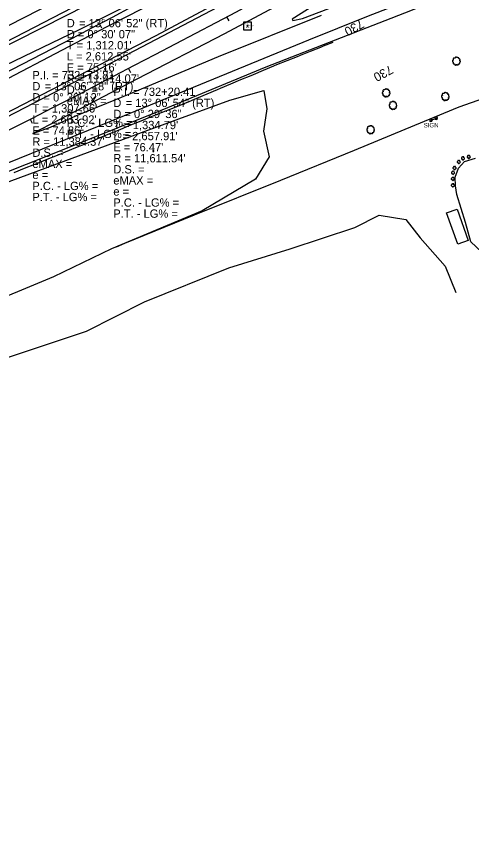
# Model space of a CAD drawing. Extents: x 1901471 to 1963503, y 756461 to 799997.
# Drawn here: x 1910625 to 1911035, y 760274 to 761023 of the extents above; entities that cross this region are included whole.
import ezdxf

# ---------------------------------------------------------------- set-up
doc = ezdxf.new("R2010")
doc.units = 0
for name, color, linetype in [('Default', 7, 'Continuous'), ('RD_DTM_BkLn1', 7, 'Continuous'), ('RD_EX_Bldg', 7, 'Continuous'), ('RD_EX_Conc', 7, 'Continuous'), ('RD_EX_Fence_Other', 7, 'Continuous'), ('RD_EX_H2O', 7, 'Continuous'), ('RD_EX_Road', 7, 'Continuous'), ('RD_EX_Road_txCode', 7, 'Continuous'), ('RD_EX_VEG', 7, 'Continuous'), ('RD_HC_Cl', 7, 'Continuous'), ('RD_HC_Data', 7, 'Continuous'), ('RD_HC_Data_Tic', 7, 'Continuous'), ('RD_HC_Survey', 7, 'Continuous'), ('RD_HC_TX_Sta50', 7, 'Continuous'), ('RD_HC_txCode', 7, 'Continuous'), ('RD_SMD_Locator', 7, 'Continuous')]:
    doc.layers.add(name, color=color, linetype=linetype)

# ---------------------------------------------------------------- blocks, each defined once
blk = doc.blocks.new('T2')
at = {"layer": 'RD_EX_VEG'}
for points in [[(0.05233333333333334, 7.213166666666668), (-0.24750000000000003, 7.238166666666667), (-0.5723333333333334, 7.138166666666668), (-0.8222500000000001, 7.038250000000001), (-1.0471666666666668, 6.963250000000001), (-1.2720833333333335, 6.863250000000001), (-1.5719166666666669, 6.688416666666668), (-1.7968333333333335, 6.488416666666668), (-1.9218333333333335, 6.2385833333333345), (-1.9718333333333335, 6.013666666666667), (-2.0217500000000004, 5.738833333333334), (-2.0217500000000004, 5.563833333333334), (-2.146666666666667, 5.538833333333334), (-2.296666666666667, 5.563833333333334), (-2.5465000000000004, 5.638833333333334), (-2.796416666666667, 5.638833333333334), (-3.0463333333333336, 5.638833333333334), (-3.3961666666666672, 5.613833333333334), (-3.7460000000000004, 5.613833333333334), (-4.020833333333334, 5.563833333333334), (-4.345750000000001, 5.513916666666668), (-4.720583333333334, 5.389000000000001), (-5.0704166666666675, 5.264000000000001), (-5.37025, 5.014083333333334), (-5.620166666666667, 4.539333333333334), (-5.745166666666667, 4.189500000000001), (-5.895083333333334, 3.9395833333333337), (-5.745166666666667, 3.489833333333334), (-5.570166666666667, 3.139916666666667), (-5.545250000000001, 2.9400000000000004), (-5.470250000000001, 2.5152500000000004), (-5.37025, 2.2903333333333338), (-5.245333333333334, 2.0903333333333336), (-5.320250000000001, 2.065416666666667), (-5.695166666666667, 2.015416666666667), (-5.995000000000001, 1.9155000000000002), (-6.419833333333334, 1.6905833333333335), (-6.644750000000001, 1.465666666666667), (-6.744750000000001, 1.1407500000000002), (-6.769666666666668, 0.7909166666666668), (-6.869583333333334, 0.5910833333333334), (-6.944583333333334, 0.3161666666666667), (-6.969583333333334, 0.2411666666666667), (-7.019583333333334, -0.08366666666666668), (-6.9195833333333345, -0.5335000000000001), (-6.894583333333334, -0.8833333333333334), (-6.769666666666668, -1.1082500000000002), (-6.619750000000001, -1.2830833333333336), (-6.444833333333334, -1.5330000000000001), (-6.045000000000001, -1.7579166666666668), (-5.7201666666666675, -1.8579166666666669), (-5.520250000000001, -1.8828333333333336), (-5.695166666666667, -2.382666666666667), (-5.745166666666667, -2.7325000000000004), (-5.870083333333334, -3.132333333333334), (-5.870083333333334, -3.2072500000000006), (-5.920000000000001, -3.682083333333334), (-5.770166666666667, -4.007000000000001), (-5.695166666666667, -4.38175), (-5.520250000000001, -4.606666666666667), (-5.245333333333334, -4.906583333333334), (-4.9205000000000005, -5.131416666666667), (-4.420666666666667, -5.256416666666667), (-4.020833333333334, -5.231416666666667), (-3.4460833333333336, -5.056500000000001), (-3.1962500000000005, -4.9815000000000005), (-3.2212500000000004, -5.156416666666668), (-3.1962500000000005, -5.531333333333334), (-3.1962500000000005, -5.956083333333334), (-3.0463333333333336, -6.280916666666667), (-2.946333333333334, -6.555833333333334), (-2.796416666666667, -6.805750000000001), (-2.4715000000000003, -7.030583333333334), (-2.07175, -7.1055833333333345), (-1.6469166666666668, -7.2555000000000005), (-1.1970833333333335, -7.330500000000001), (-0.6973333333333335, -7.355500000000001), (-0.09758333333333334, -7.205583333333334), (0.17725000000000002, -7.080583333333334), (0.27725000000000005, -6.905666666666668), (0.47716666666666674, -6.530833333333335), (0.4271666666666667, -6.3059166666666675), (0.4521666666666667, -5.706166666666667), (0.5520833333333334, -5.881166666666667), (0.7270833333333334, -6.231000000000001), (1.2268333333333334, -6.530833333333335), (1.626666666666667, -6.705750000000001), (2.101416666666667, -6.8557500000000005), (2.4013333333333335, -6.930666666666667), (2.8760833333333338, -6.8557500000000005), (3.2510000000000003, -6.780750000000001), (3.6257500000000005, -6.655750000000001), (3.9256666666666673, -6.380916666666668), (4.100583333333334, -6.106000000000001), (4.1505833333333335, -5.831166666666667), (4.2255, -5.456333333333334), (4.275500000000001, -5.281416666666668)], [(4.275500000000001, -5.281416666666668), (4.200583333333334, -5.106416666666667), (4.1505833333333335, -4.856583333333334), (4.2255, -4.881583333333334), (4.4004166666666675, -4.931583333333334), (4.675333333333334, -5.056500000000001), (4.900250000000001, -5.131416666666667), (5.225083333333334, -5.106416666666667), (5.500000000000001, -5.006500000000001), (5.949750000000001, -4.731583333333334), (6.224666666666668, -4.256833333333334), (6.499500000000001, -3.8570000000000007), (6.5745000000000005, -3.5321666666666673), (6.524500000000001, -3.3072500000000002), (6.499500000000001, -2.8075000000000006), (6.299583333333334, -2.5575833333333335), (6.249583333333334, -2.432666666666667), (6.1496666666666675, -2.0328333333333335), (6.224666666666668, -1.9828333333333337), (6.499500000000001, -1.9328333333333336), (6.874333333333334, -1.8079166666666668), (7.149250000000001, -1.6830000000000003), (7.374166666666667, -1.5080000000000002), (7.449083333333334, -1.2830833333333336), (7.424166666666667, -0.8833333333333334), (7.4740833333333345, -0.48350000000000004), (7.399166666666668, -0.3335), (7.299166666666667, -0.1836666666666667), (7.224166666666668, 0.016333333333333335), (7.074250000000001, 0.16616666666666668), (6.974333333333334, 0.3161666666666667), (6.874333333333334, 0.41608333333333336), (6.749416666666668, 0.5660833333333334), (6.5745000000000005, 0.6910000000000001), (6.424583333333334, 0.7410000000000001), (6.374583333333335, 0.8909166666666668), (6.524500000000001, 1.0908333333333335), (6.5745000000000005, 1.1907500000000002), (6.599416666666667, 1.4156666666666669), (6.824416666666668, 1.7655000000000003), (6.874333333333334, 2.1653333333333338), (6.824416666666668, 2.590166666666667), (6.774416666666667, 2.8650833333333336), (6.624416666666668, 3.139916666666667), (6.424583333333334, 3.3898333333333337), (6.299583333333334, 3.5647500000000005), (6.124666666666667, 3.689666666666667), (5.799833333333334, 3.814666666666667), (5.549916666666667, 3.864583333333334), (5.200083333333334, 3.864583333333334), (5.000166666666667, 3.9145833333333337), (5.025166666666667, 3.964583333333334), (5.025166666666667, 4.1145000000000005), (5.025166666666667, 4.389416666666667), (4.950166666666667, 4.839166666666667), (4.800250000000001, 5.339), (4.800250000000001, 5.364000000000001), (4.7002500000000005, 5.613833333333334), (4.475416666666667, 5.813750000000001), (4.3005, 5.913666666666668), (4.100583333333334, 6.038666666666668), (3.850666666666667, 6.063666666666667), (3.5508333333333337, 6.063666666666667), (3.2759166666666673, 6.013666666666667), (3.0760000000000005, 5.913666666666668), (2.9010833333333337, 5.788750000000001), (2.8260833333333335, 5.938666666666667), (2.726166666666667, 6.2385833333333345), (2.676166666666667, 6.3885000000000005), (2.52625, 6.563416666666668), (2.301416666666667, 6.7633333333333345), (1.8515000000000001, 6.888250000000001), (1.2268333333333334, 6.813333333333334), (0.9269166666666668, 6.613416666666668), (0.7770000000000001, 6.438500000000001), (0.7270833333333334, 6.563416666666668), (0.5270833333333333, 6.7633333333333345), (0.4271666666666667, 6.938250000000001), (0.25225000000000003, 7.063250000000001), (0.10233333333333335, 7.163166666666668), (0.0023333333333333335, 7.213166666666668)]]:
    blk.add_spline(points, degree=3, dxfattribs=at)
blk = doc.blocks.new('SB2')
at = {"layer": 'RD_EX_VEG'}
for centre, radius, start, end in [((-1.563757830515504, -0.1555935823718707), 1.256970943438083, 96.45178611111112, 294.73400833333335), ((-0.7210660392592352, 1.5471418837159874), 1.0835094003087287, 34.97628888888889, 204.7560222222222), ((1.0452472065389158, 1.7020636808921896), 0.9945285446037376, 308.76261111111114, 152.04674444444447), ((1.8396429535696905, -0.2793298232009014), 1.2180790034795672, 256.56668055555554, 98.10463055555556), ((0.2455500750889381, -1.5963122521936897), 1.3177675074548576, 166.88265555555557, 5.758930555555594)]:
    blk.add_arc(centre, radius, start, end, dxfattribs=at)
blk = doc.blocks.new('SIGNPOST')
at = {"layer": 'Default'}
for centre, start, end in [((7.776250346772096e-18, 0), 90.00000000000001, 270), ((-7.776250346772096e-18, 0), 270, 90)]:
    blk.add_arc(centre, 0.12700000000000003, start, end, dxfattribs=at)

msp = doc.modelspace()

# ---------------------------------------------------------------- linework, layer by layer
at = {"layer": 'Default'}
for p, q in [((1910704.7770000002, 760975.9843000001), (1910704.7770000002, 760974.2343000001)), ((1910705.6520000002, 760975.1093000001), (1910703.9020000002, 760975.1093000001)), ((1910674.5337000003, 760917.9531000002), (1910672.7837000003, 760917.9531000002)), ((1910673.6587000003, 760918.8281000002), (1910673.6587000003, 760917.0781000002)), ((1910748.9604000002, 760901.2138000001), (1910747.2104000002, 760901.2138000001)), ((1910748.0854000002, 760902.0888000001), (1910748.0854000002, 760900.3388000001))]:
    msp.add_line(p, q, dxfattribs=at)
at = {"layer": 'RD_DTM_BkLn1'}
msp.add_lwpolyline([(1910622.6313006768, 760881.9708389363), (1910631.922190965, 760885.6664134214), (1910641.2130812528, 760889.3619879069), (1910643.064136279, 760890.0982695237), (1910652.3296787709, 760893.8574605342), (1910661.5952212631, 760897.6166515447), (1910668.9848766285, 760900.6147626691), (1910678.2430306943, 760904.3939292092), (1910687.5011847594, 760908.173095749), (1910696.7593388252, 760911.9522622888), (1910698.0908794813, 760912.4957954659), (1910707.3210735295, 760916.3411197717), (1910716.5512675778, 760920.1864440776), (1910725.781461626, 760924.0317683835), (1910726.3550362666, 760924.270721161), (1910735.633826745, 760927.9940825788), (1910744.9126172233, 760931.7174439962), (1910750.0804685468, 760933.7911817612), (1910759.3518262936, 760937.5329661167), (1910768.6231840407, 760941.2747504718), (1910777.8945417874, 760945.0165348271), (1910778.174266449, 760945.1294276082), (1910787.3955065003, 760948.9938692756), (1910796.6167465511, 760952.8583109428), (1910805.8379866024, 760956.72275261), (1910808.6637450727, 760957.906972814), (1910817.8753922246, 760961.7951290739), (1910827.087039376, 760965.6832853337), (1910836.2986865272, 760969.5714415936), (1910838.3418913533, 760970.4338606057), (1910847.5396088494, 760974.354475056), (1910856.7373263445, 760978.2750895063), (1910859.4643495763, 760979.4375090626), (1910868.782821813, 760983.0639470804), (1910878.1012940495, 760986.6903850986), (1910880.7117837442, 760987.7063004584), (1910889.9869461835, 760991.4417091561), (1910899.262108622, 760995.1771178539), (1910901.739897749, 760996.1750038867), (1910910.361455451, 760999.3981055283)], dxfattribs=at)
at = {"layer": 'RD_EX_Bldg'}
msp.add_lwpolyline([(1910998.4000000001, 760929.1900000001), (1911004.5700000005, 760931.3600000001)], dxfattribs=at)
at = {"layer": 'RD_EX_Conc'}
msp.add_lwpolyline([(1911022.6600000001, 760817.2200000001), (1911012.6700000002, 760845.4000000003), (1911022.0300000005, 760848.7200000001), (1911032.0200000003, 760820.5300000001)], close=True, dxfattribs=at)
at = {"layer": 'RD_EX_Fence_Other'}
for points in [[(1910580.8800000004, 760962.4200000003), (1910681.6500000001, 761011.1200000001), (1910824.1700000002, 761083.3400000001), (1910922.5400000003, 761136.0100000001), (1911091.9300000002, 761226.7000000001), (1911190.0700000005, 761280.4500000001), (1911287.4800000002, 761335.9900000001), (1911356.1000000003, 761375.9400000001), (1911439.3500000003, 761425.0100000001), (1911494.0600000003, 761458.0000000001), (1911589.0700000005, 761516.1800000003), (1911670.89, 761566.9300000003), (1911753.1900000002, 761616.7100000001), (1911806.6900000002, 761651.1400000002), (1911873.1500000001, 761696.0100000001), (1911887.0700000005, 761707.4100000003), (1911902.9000000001, 761720.8400000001)], [(1910714.7600000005, 760814.7800000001), (1910722.4100000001, 760818.1800000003), (1910785.1700000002, 760843.5400000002), (1910863.0500000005, 760874.82), (1910929.5100000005, 760902.1100000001), (1910983.9100000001, 760924.5000000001), (1911023.9700000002, 760941.0200000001), (1911091.6600000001, 760964.81), (1911105.1200000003, 760968.7500000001), (1911126.4600000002, 760976.6200000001), (1911147.9800000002, 760983.0900000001), (1911206.5700000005, 760997.7800000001), (1911243.1300000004, 761005.9200000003), (1911277.9400000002, 761012.9100000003), (1911301.9000000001, 761016.7600000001), (1911361.1900000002, 761026.56)], [(1911049.3800000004, 760805.1900000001), (1911034.4300000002, 760819.2000000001), (1911029.5500000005, 760836.83), (1911021.8300000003, 760862.0200000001), (1911020.7300000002, 760869.8900000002), (1911020.4200000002, 760877.6000000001), (1911023.2500000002, 760885.6300000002), (1911028.9200000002, 760891.7700000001), (1911038.6800000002, 760894.7600000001)]]:
    msp.add_lwpolyline(points, dxfattribs=at)
at = {"layer": 'RD_EX_H2O'}
msp.add_lwpolyline([(1909887.3000000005, 760625.4900000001), (1909934.2500000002, 760644.2800000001), (1910017.4500000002, 760680.8900000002), (1910099.7900000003, 760717.7600000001), (1910182.8200000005, 760756.1200000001), (1910236.6900000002, 760780.7800000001), (1910299.4900000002, 760809.82), (1910379.1900000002, 760848.3500000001), (1910428.0700000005, 760871.7000000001), (1910474.6600000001, 760894.6400000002), (1910580.3500000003, 760947.83), (1910696.5500000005, 761008.4900000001), (1910820.6200000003, 761072.3), (1910918.7000000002, 761126.2600000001), (1910925.4000000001, 761129.6100000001)], dxfattribs=at)
at = {"layer": 'RD_EX_Road'}
for points in [[(1910555.9700000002, 760966.08), (1910670.1800000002, 761023.8400000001), (1910732.0500000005, 761055.7700000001), (1910873.2500000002, 761130.9700000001), (1911013.1300000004, 761208.81), (1911171.1100000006, 761300.4700000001), (1911315.5900000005, 761384.8900000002), (1911418.2800000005, 761447.5900000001), (1911490.6900000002, 761492.6800000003), (1911567.3700000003, 761541.8800000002), (1911693.4300000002, 761624.33), (1911806.9700000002, 761700.8500000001), (1911899.7900000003, 761762.4000000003), (1911913.9200000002, 761772.8600000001), (1911956.0900000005, 761800.7400000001), (1911999.2000000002, 761829.9900000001)], [(1910580.0600000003, 760981.9200000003), (1910675.3100000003, 761030.7600000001), (1910773.4900000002, 761082.4000000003), (1910822.5800000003, 761108.6700000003), (1910885.9600000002, 761143.0300000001), (1910949.0700000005, 761177.6500000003), (1911003.9000000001, 761208.57), (1911064.7300000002, 761242.9300000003), (1911147.8600000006, 761291.2600000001), (1911222.0700000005, 761334.9300000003), (1911278.8100000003, 761368.4000000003), (1911332.8800000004, 761400.8500000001), (1911389.7500000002, 761435.3500000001), (1911475.1800000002, 761488.1300000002), (1911593.1200000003, 761563.1100000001), (1911672.9500000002, 761615.9000000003), (1911716.8100000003, 761645.5400000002), (1911779.8000000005, 761687.9400000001), (1911835.9000000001, 761725.3700000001), (1911887.8000000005, 761759.8600000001), (1911937.9100000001, 761793.33), (1911981.0100000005, 761822.4600000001), (1911998.6300000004, 761834.4100000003)], [(1910605.0100000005, 760930.3700000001), (1910750.1600000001, 761005.4100000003), (1910935.4500000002, 761104.6400000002), (1911040.1100000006, 761163.3900000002), (1911146.4200000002, 761223.7800000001), (1911234.6300000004, 761274.9600000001), (1911353.7700000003, 761346.3800000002), (1911491.3400000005, 761430.8), (1911642.0800000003, 761526.4100000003), (1911754.64, 761601.2900000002), (1911848.4400000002, 761663.33), (1911899.7900000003, 761698.2200000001), (1911993.7900000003, 761761.3900000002), (1912007.0300000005, 761770.2900000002)], [(1910589.3400000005, 760918.2400000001), (1910700.4300000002, 760975.7100000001), (1910824.9500000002, 761041.33), (1910949.7100000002, 761108.6300000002), (1911067.5200000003, 761174.7300000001), (1911186.5300000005, 761242.7500000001), (1911299.7700000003, 761309.2100000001), (1911392.1500000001, 761365.3600000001), (1911489.0800000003, 761425.2200000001), (1911580.9700000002, 761483.4000000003), (1911680.7900000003, 761547.5900000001), (1911813.4700000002, 761635.6400000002), (1911899.7800000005, 761693.1700000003), (1911931.1500000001, 761714.4000000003), (1911978.2000000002, 761746.0200000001), (1912007.6200000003, 761765.9400000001)], [(1910585.7400000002, 760878.06), (1910710.5000000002, 760928.56), (1910888.2900000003, 761001.6200000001), (1910940.6000000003, 761022.7400000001), (1910979.4700000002, 761037.9700000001), (1911045.6900000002, 761063.8800000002), (1911129.1800000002, 761091.6000000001), (1911194.2000000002, 761107.9100000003), (1911276.0200000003, 761125.07), (1911337.2000000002, 761133.4600000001), (1911445.1700000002, 761144.3800000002), (1911566.3400000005, 761156.2600000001), (1911684.3800000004, 761167.8900000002), (1911741.9700000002, 761173.4100000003), (1911807.2300000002, 761177.7300000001), (1911899.39, 761184.4200000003), (1911950.14, 761188.5300000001), (1911980.8000000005, 761190.4700000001), (1911998.7200000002, 761190.6900000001), (1912012.5400000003, 761189.3900000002), (1912024.6300000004, 761186.8)], [(1911898.8000000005, 761179.0200000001), (1911785.9100000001, 761169.1500000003), (1911700.3400000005, 761161.58), (1911583.1700000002, 761149.7300000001), (1911418.2800000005, 761134.1000000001), (1911324.1500000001, 761123.7300000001), (1911252.4000000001, 761112.2100000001), (1911180.9800000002, 761095.7500000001), (1911047.6800000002, 761055.4400000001), (1910980.2100000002, 761027.7900000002), (1910849.6300000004, 760977.0200000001), (1910755.8200000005, 760938.1500000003), (1910677.8100000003, 760906.7700000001), (1910499.5700000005, 760835.6900000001), (1910338.5000000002, 760760.5400000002), (1910201.4000000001, 760696.8700000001), (1909857.8700000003, 760545.9200000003), (1909713.0200000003, 760487.06), (1909551.9400000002, 760422.8900000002), (1909472.4100000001, 760392.4500000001), (1909224.6300000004, 760297.56), (1909135.3400000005, 760263.3900000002), (1909100.5900000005, 760249.4700000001)], [(1910901.2500000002, 761054.8900000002), (1910812.2300000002, 761007.1400000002), (1910733.3000000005, 760965.9900000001), (1910685.7900000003, 760941.1600000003), (1910639.4800000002, 760916.9300000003), (1910655.3200000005, 760922.9200000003), (1910678.1100000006, 760933.0000000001), (1910725.8600000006, 760952.4400000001), (1910806.9500000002, 760986.5100000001), (1910899.8100000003, 761023.81)], [(1910929.5300000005, 761056.2600000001), (1910873.2500000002, 761020.3800000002), (1910873.9100000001, 761019.07), (1910882.7900000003, 761021.0400000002), (1910921.3000000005, 761035.5200000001)]]:
    msp.add_lwpolyline(points, dxfattribs=at)
at = {"layer": 'RD_EX_VEG'}
for points in [[(1910612.2500000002, 760871.6100000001), (1910737.5100000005, 760918.0900000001), (1910817.0800000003, 760947.2400000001), (1910847.8000000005, 760955.9000000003), (1910850.5600000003, 760939.3600000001), (1910847.4000000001, 760919.2700000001), (1910852.5300000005, 760896.0300000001), (1910840.3100000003, 760875.9400000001), (1910792.2600000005, 760847.1900000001), (1910710.3300000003, 760812.9200000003), (1910657.9400000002, 760787.5200000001), (1910587.8300000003, 760758.3700000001)], [(1910147.2500000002, 760468.4600000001), (1910143.6300000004, 760484.7700000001), (1910152.9900000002, 760504.2200000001), (1910276.9100000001, 760568.3400000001), (1910398.6600000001, 760628.8600000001), (1910500.2400000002, 760676.4100000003), (1910606.3400000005, 760711.4900000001), (1910687.8800000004, 760738.6700000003), (1910740.2700000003, 760765.06), (1910816.2900000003, 760795.7900000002), (1910871.4300000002, 760812.9200000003), (1910929.7300000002, 760832.2200000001), (1910951.7900000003, 760843.2500000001), (1910975.8100000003, 760839.31), (1910988.8100000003, 760822.7700000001), (1911011.2600000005, 760797.1700000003), (1911020.9400000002, 760773.5400000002)]]:
    msp.add_lwpolyline(points, dxfattribs=at)
at = {"layer": 'RD_HC_Cl'}
for centre, radius, start, end in [((1905408.2458716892, 771170.6492824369), 11414.0664, 290.894469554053, 304.0088245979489), ((1905390.191717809, 771086.470862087), 11384.366000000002, 290.90340658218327, 304.0085286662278), ((1905358.488046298, 771272.4106571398), 11611.5386, 290.90197060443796, 304.0171003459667)]:
    msp.add_arc(centre, radius, start, end, dxfattribs=at)
at = {"layer": 'RD_HC_Data_Tic'}
for p, q in [((1910814.2337787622, 761022.4025028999), (1910816.11320092, 761018.8715296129)), ((1910699.4848115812, 761015.9596503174), (1910701.3502797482, 761012.421285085)), ((1910725.7582163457, 760975.7976421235), (1910727.6071600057, 760972.2506141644)), ((1910636.8845731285, 760929.956462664), (1910638.7029011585, 760926.3936431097))]:
    msp.add_line(p, q, dxfattribs=at)
at = {"layer": 'RD_HC_Survey'}
msp.add_lwpolyline([(1910836.5245339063, 761017.7445339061), (1910829.4534660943, 761017.7445339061), (1910829.4534660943, 761010.6734660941), (1910836.5245339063, 761010.6734660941)], close=True, dxfattribs=at)
msp.add_circle((1910832.9890000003, 761014.2090000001), 0.5000000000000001, dxfattribs=at)
at = {"layer": 'RD_SMD_Locator'}
msp.add_circle((1910832.9890000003, 761014.2090000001), 0.001, dxfattribs=at)

# ---------------------------------------------------------------- block references
at = {"layer": 'RD_EX_Bldg', "xscale": 9.84251968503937, "yscale": 9.84251968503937}
for p in [(1911003.3000000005, 760930.82), (1910998.4000000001, 760929.1900000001)]:
    msp.add_blockref('SIGNPOST', p, dxfattribs=at)
at = {"layer": 'RD_EX_VEG'}
for name, p, xscale, yscale in [('T2', (1911021.3800000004, 760982.4600000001), 0.4921259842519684, 0.4921259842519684), ('T2', (1910958.0000000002, 760953.7600000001), 0.4921259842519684, 0.4921259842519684), ('T2', (1911011.4000000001, 760950.4900000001), 0.4921259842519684, 0.4921259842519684), ('T2', (1910964.1800000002, 760942.5000000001), 0.4921259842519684, 0.4921259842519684), ('T2', (1910944.0200000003, 760920.5300000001), 0.4921259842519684, 0.4921259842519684), ('SB2', (1911027.3200000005, 760894.7100000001), 0.5019685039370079, 0.5019685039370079), ('SB2', (1911032.5100000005, 760895.9700000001), 0.5019685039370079, 0.5019685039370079), ('SB2', (1911019.7600000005, 760885.9000000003), 0.5019685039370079, 0.5019685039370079), ('SB2', (1911023.5400000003, 760891.4100000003), 0.5019685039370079, 0.5019685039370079), ('SB2', (1911018.3400000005, 760881.6500000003), 0.5019685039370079, 0.5019685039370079), ('SB2', (1911018.1900000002, 760876.1400000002), 0.5019685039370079, 0.5019685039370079), ('SB2', (1911018.1900000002, 760870.31), 0.5019685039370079, 0.5019685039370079)]:
    msp.add_blockref(name, p, dxfattribs=dict(at, xscale=xscale, yscale=yscale))

# ---------------------------------------------------------------- texts
at = {"layer": 'Default'}
for s, p in [('522', (1910703.595897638, 760977.3093000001)), ('508', (1910672.4382275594, 760920.1531000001)), ('537', (1910746.9042976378, 760903.4138000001))]:
    msp.add_text(s, height=1.0000000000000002, dxfattribs=at).set_placement(p)
at = {"layer": 'RD_EX_Road'}
msp.add_text('SIGN', height=4.000000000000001, dxfattribs=at).set_placement((1910991.9500000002, 760922.57))
at = {"layer": 'RD_EX_Road_txCode'}
msp.add_text('397.430', height=1.0000000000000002, dxfattribs=at).set_placement((1910833.9890000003, 761013.7090000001))
at = {"layer": 'RD_HC_Data'}
for s, p in [('    = 13%%d 06\' 52" (RT)', (1910670.0000000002, 761013.0000000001)), ('D', (1910670.0000000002, 761013.0000000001)), ('D = 0%%d 30\' 07"', (1910670.0000000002, 761003.0000000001)), ("T = 1,312.01'", (1910670.0000000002, 760993.0000000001)), ("L = 2,612.55'", (1910670.0000000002, 760983.0000000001)), ("E = 75.16'", (1910670.0000000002, 760973.0000000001)), ('P.I. = 732+73.81', (1910639.0000000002, 760966.0000000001)), ("R = 11,414.07'", (1910670.0000000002, 760963.0000000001)), ('D', (1910639.0000000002, 760956.0000000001)), ('    = 13%%d 06\' 18" (RT)', (1910639.0000000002, 760956.0000000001)), ('D = 0%%d 30\' 12"', (1910639.0000000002, 760946.0000000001)), ('D.S. = ', (1910670.0000000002, 760953.0000000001)), ('P.I. = 732+20.41', (1910712.0000000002, 760951.0000000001)), ('eMAX = ', (1910670.0000000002, 760943.0000000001)), ('D', (1910712.0000000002, 760941.0000000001)), ('    = 13%%d 06\' 54" (RT)', (1910712.0000000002, 760941.0000000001)), ("T = 1,307.66'", (1910639.0000000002, 760936.0000000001)), ('e = ', (1910670.0000000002, 760933.0000000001)), ('D = 0%%d 29\' 36"', (1910712.0000000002, 760931.0000000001)), ("L = 2,603.92'", (1910639.0000000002, 760926.0000000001)), ("E = 74.86'", (1910639.0000000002, 760916.0000000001)), ('P.C. - LG% = ', (1910670.0000000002, 760923.0000000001)), ("T = 1,334.79'", (1910712.0000000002, 760921.0000000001)), ('P.T. - LG% = ', (1910670.0000000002, 760913.0000000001)), ("L = 2,657.91'", (1910712.0000000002, 760911.0000000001)), ("R = 11,384.37'", (1910639.0000000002, 760906.0000000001)), ("E = 76.47'", (1910712.0000000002, 760901.0000000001)), ('D.S. = ', (1910639.0000000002, 760896.0000000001)), ('eMAX = ', (1910639.0000000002, 760886.0000000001)), ("R = 11,611.54'", (1910712.0000000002, 760891.0000000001)), ('D.S. = ', (1910712.0000000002, 760881.0000000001)), ('e = ', (1910639.0000000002, 760876.0000000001)), ('eMAX = ', (1910712.0000000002, 760871.0000000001)), ('P.C. - LG% = ', (1910639.0000000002, 760866.0000000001)), ('P.T. - LG% = ', (1910639.0000000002, 760856.0000000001)), ('e = ', (1910712.0000000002, 760861.0000000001)), ('P.C. - LG% = ', (1910712.0000000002, 760851.0000000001)), ('P.T. - LG% = ', (1910712.0000000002, 760841.0000000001))]:
    msp.add_text(s, height=7.500000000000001, dxfattribs=at).set_placement(p)
at = {"layer": 'RD_HC_TX_Sta50'}
for height, rotation, p in [(8, 208.80530010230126, (1910935.2660078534, 761020.3542485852)), (8.000000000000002, 208.51835800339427, (1910961.5424058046, 760979.0417663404))]:
    msp.add_text('730', height=height, rotation=rotation, dxfattribs=at).set_placement(p)
at = {"layer": 'RD_HC_txCode'}
for s, p in [('8039', (1910831.3197086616, 761015.2090000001)), ('MSC', (1910831.6740393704, 761012.2090000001))]:
    msp.add_text(s, height=1.0000000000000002, dxfattribs=at).set_placement(p)

doc.saveas('drawing.dxf')
